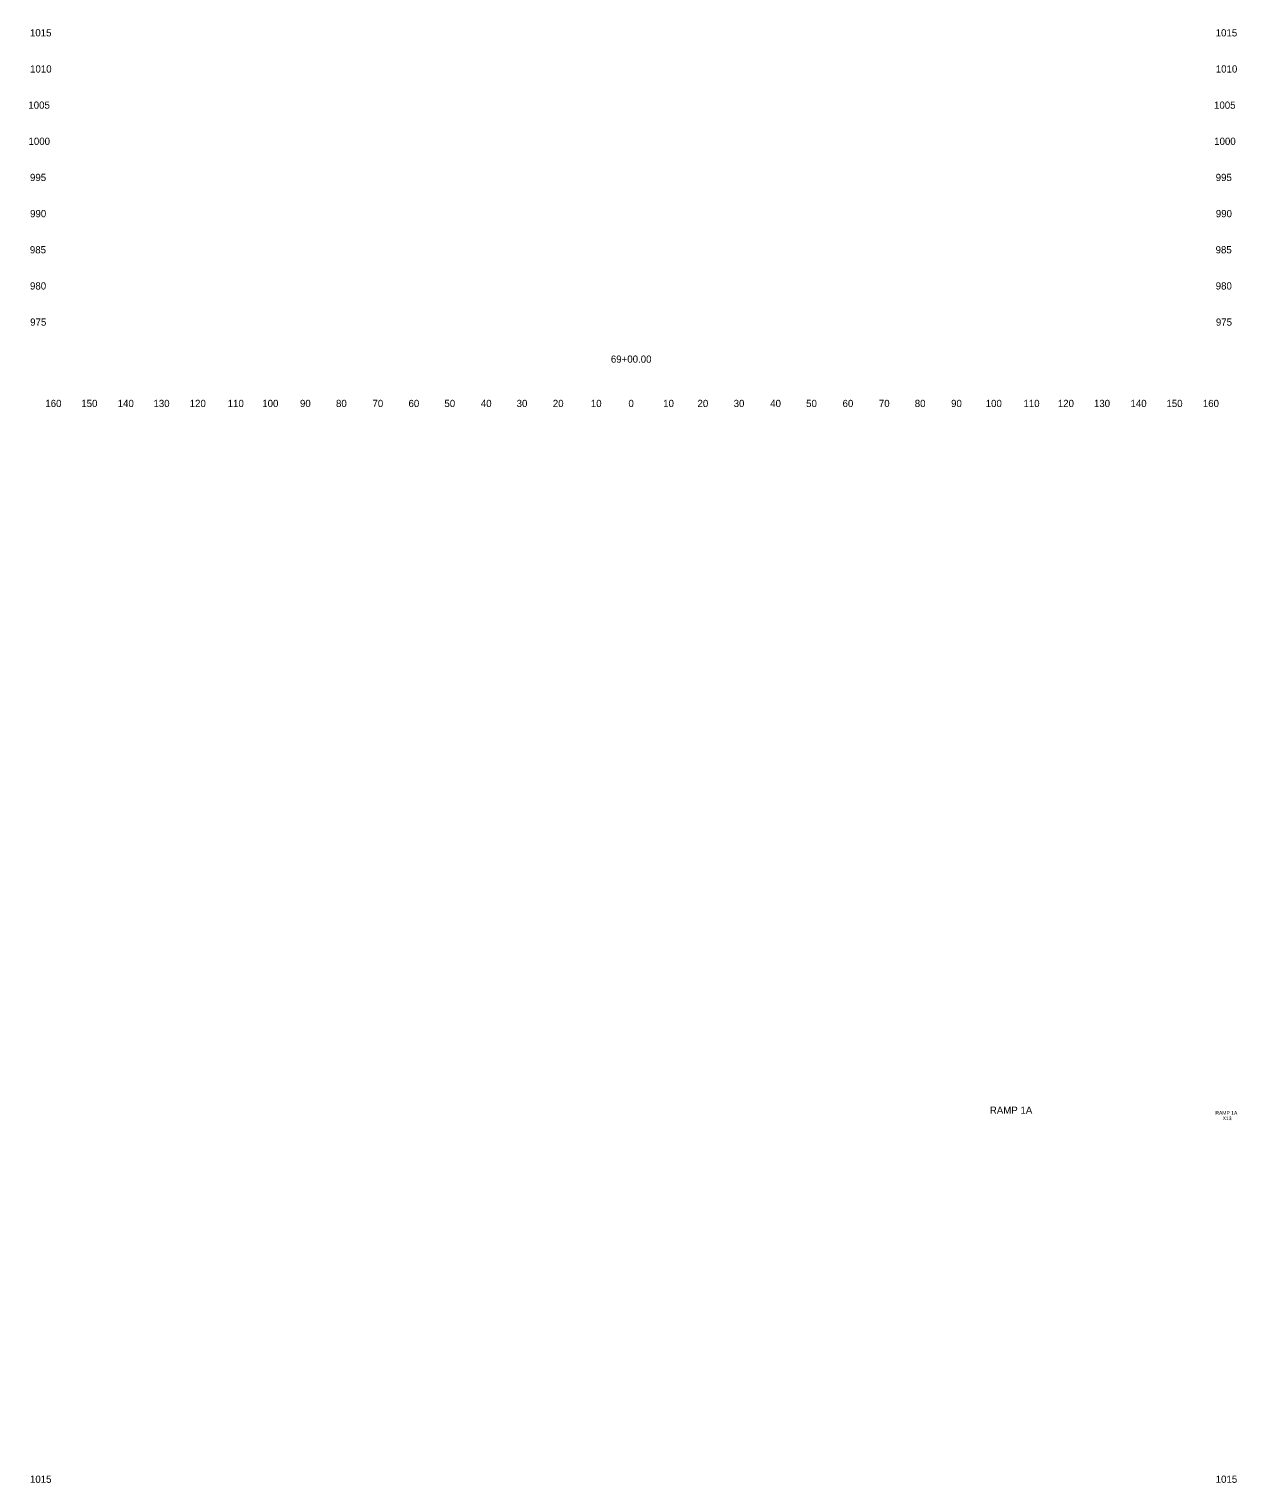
# Model space of a CAD drawing. Extents: x 4994 to 6873, y 4997 to 8804.
# Drawn here: x 5508.6 to 5842.5, y 5900 to 6302 of the extents above; entities that cross this region are included whole.
import ezdxf

# ---------------------------------------------------------------- set-up
doc = ezdxf.new("R2010")
doc.units = 0
for name, color, linetype in [('RD_SHT_ID', 7, 'Continuous'), ('RD_XS_TX_Offset', 7, 'Continuous'), ('RD_XS_TX_Station', 7, 'Continuous')]:
    doc.layers.add(name, color=color, linetype=linetype)

msp = doc.modelspace()

# ---------------------------------------------------------------- texts
at = {"layer": 'RD_SHT_ID'}
for s, height, p in [('RAMP 1A', 2, (5774.21, 6002.06)), ('RAMP 1A', 1, (5836.57, 6001.8)), ('X13', 1, (5838.57, 6000.3))]:
    msp.add_text(s, height=height, dxfattribs=at).set_placement(p)
at = {"layer": 'RD_XS_TX_Offset'}
for s, p in [('1015', (5508.85, 6300)), ('1015', (5836.65, 6300)), ('1010', (5508.88, 6290)), ('1010', (5836.68, 6290)), ('1005', (5508.4, 6280)), ('1005', (5836.2, 6280)), ('1000', (5508.44, 6270)), ('1000', (5836.24, 6270)), ('995', (5508.86, 6260)), ('995', (5836.66, 6260)), ('990', (5508.89, 6250)), ('990', (5836.69, 6250)), ('985', (5508.83, 6240)), ('985', (5836.63, 6240)), ('980', (5508.86, 6230)), ('980', (5836.66, 6230)), ('975', (5508.91, 6220)), ('975', (5836.71, 6220)), ('160', (5513.1, 6197.5)), ('150', (5523.04, 6197.5)), ('140', (5533.1, 6197.5)), ('130', (5542.99, 6197.5)), ('120', (5553.01, 6197.5)), ('110', (5563.51, 6197.5)), ('100', (5573.07, 6197.5)), ('90', (5583.5, 6197.5)), ('80', (5593.46, 6197.5)), ('70', (5603.54, 6197.5)), ('60', (5613.5, 6197.5)), ('50', (5623.43, 6197.5)), ('40', (5633.5, 6197.5)), ('30', (5643.39, 6197.5)), ('20', (5653.4, 6197.5)), ('10', (5663.91, 6197.5)), ('0', (5674.3, 6197.5)), ('0', (5674.3, 6197.5)), ('10', (5683.91, 6197.5)), ('20', (5693.4, 6197.5)), ('30', (5703.39, 6197.5)), ('40', (5713.5, 6197.5)), ('50', (5723.43, 6197.5)), ('60', (5733.5, 6197.5)), ('70', (5743.54, 6197.5)), ('80', (5753.46, 6197.5)), ('90', (5763.5, 6197.5)), ('100', (5773.07, 6197.5)), ('110', (5783.51, 6197.5)), ('120', (5793.01, 6197.5)), ('130', (5802.99, 6197.5)), ('140', (5813.1, 6197.5)), ('150', (5823.04, 6197.5)), ('160', (5833.1, 6197.5)), ('1015', (5508.85, 5900)), ('1015', (5836.65, 5900))]:
    msp.add_text(s, height=2, dxfattribs=at).set_placement(p)
at = {"layer": 'RD_XS_TX_Station'}
msp.add_text('69+00.00', height=2, dxfattribs=at).set_placement((5669.45, 6209.76))

doc.saveas('drawing.dxf')
